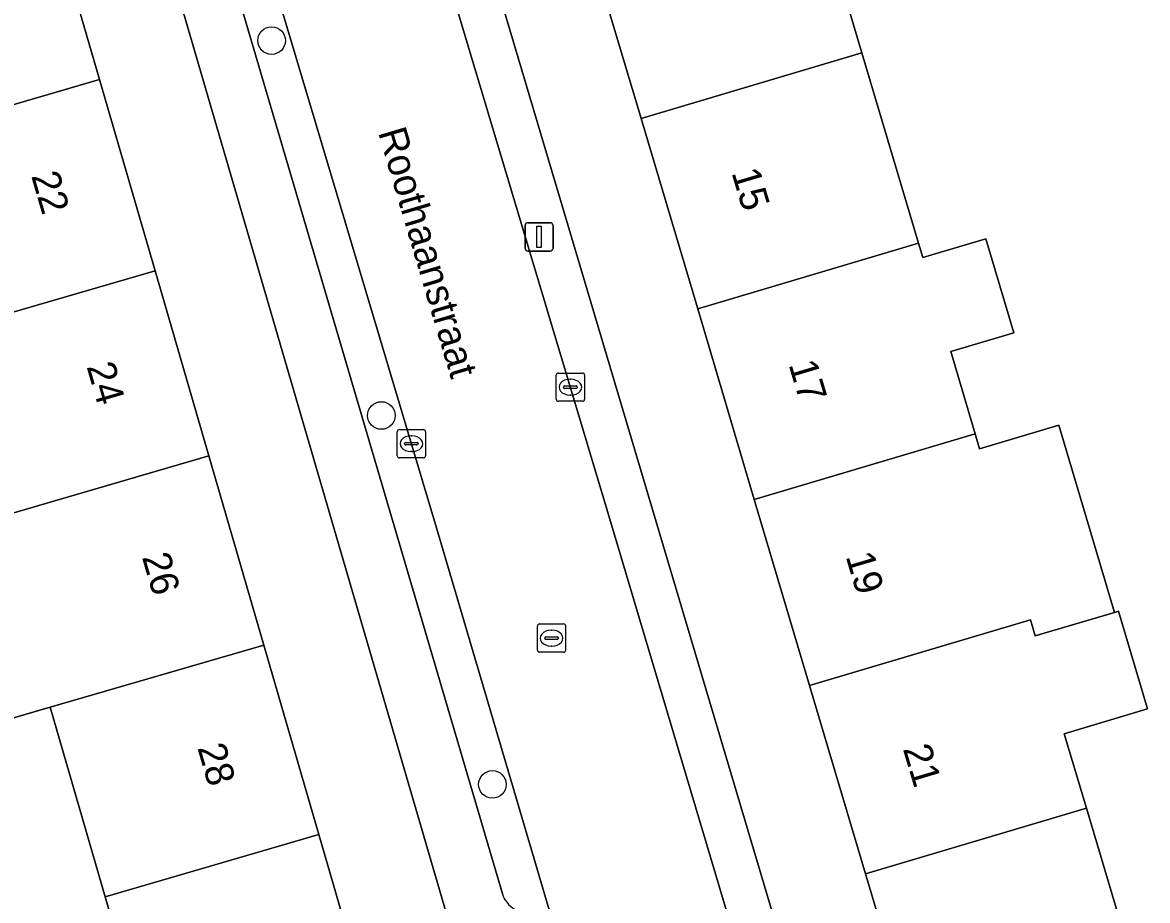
# Model space of a CAD drawing. Extents: x 162523 to 163266, y 381230 to 382050.
# Drawn here: x 162914.84 to 162954.65, y 381817.31 to 381848.37 of the extents above; entities that cross this region are included whole.
import ezdxf

# ---------------------------------------------------------------- set-up
doc = ezdxf.new("R2010")
doc.units = 0
for name, color, linetype in [('IMGEO_Boom', 7, 'Continuous'), ('IMGEO_Erf', 7, 'Continuous'), ('IMGEO_Kolk', 7, 'Continuous'), ('IMGEO_Lichtmast', 7, 'Continuous'), ('IMGEO_Openbare_ruimte_label', 7, 'Continuous'), ('IMGEO_Pand', 7, 'Continuous'), ('IMGEO_Pand_nummerreeks', 7, 'Continuous'), ('IMGEO_Parkeervlak_open', 7, 'Continuous'), ('IMGEO_Rijbaan_lokaal_open', 7, 'Continuous'), ('IMGEO_Rioolput', 7, 'Continuous'), ('IMGEO_Voetpad_open', 7, 'Continuous')]:
    doc.layers.add(name, color=color, linetype=linetype)

msp = doc.modelspace()

# ---------------------------------------------------------------- linework, layer by layer
at = {"layer": 'IMGEO_Boom'}
for centre in [(162923.656, 381847.732), (162927.542, 381834.469), (162931.471, 381821.418)]:
    msp.add_circle(centre, 0.489, dxfattribs=at)
at = {"layer": 'IMGEO_Erf'}
for points in [[(162932.72, 381806.989), (162913.026, 381874.412), (162910.321, 381883.674), (162887.637, 381875.013), (162889.095, 381870.525), (162889.197, 381870.214), (162891.814, 381871.071), (162892.93, 381867.664), (162890.312, 381866.807), (162890.373, 381866.622), (162891.358, 381863.669), (162894.356, 381864.689), (162895.466, 381861.425), (162896.618, 381858.037), (162893.62, 381857.017), (162899.056, 381840.02), (162905.21, 381821.822), (162911.331, 381802.421)], [(162913.666, 381859.797), (162915.626, 381853.053), (162917.573, 381846.353), (162919.539, 381839.585), (162921.441, 381833.041), (162923.387, 381826.346), (162925.334, 381819.645), (162927.278, 381812.956)], [(162942.534, 381854.047), (162944.541, 381847.299), (162946.546, 381840.56), (162946.697, 381840.054), (162948.932, 381840.718), (162949.92, 381837.396), (162947.685, 381836.731), (162948.549, 381833.825), (162948.707, 381833.295), (162951.508, 381834.128), (162953.478, 381827.505), (162953.621, 381827.547), (162954.649, 381824.087), (162951.705, 381823.212), (162952.49, 381820.574), (162954.728, 381813.049)], [(162919.718, 381810.759), (162917.774, 381817.447), (162915.827, 381824.149), (162913.064, 381823.346)]]:
    msp.add_lwpolyline(points, dxfattribs=at)
msp.add_lwpolyline([(162938.733, 381838.237), (162936.729, 381844.976), (162934.721, 381851.724), (162932.793, 381858.209), (162929.389, 381857.197), (162943.516, 381809.691), (162946.922, 381810.704), (162944.677, 381818.251), (162942.694, 381824.919), (162940.736, 381831.502)], close=True, dxfattribs=at)
at = {"layer": 'IMGEO_Kolk'}
for p, q in [((162933.729, 381835.045), (162933.729, 381835.897)), ((162933.804, 381835.971), (162934.656, 381835.971)), ((162934.73, 381835.897), (162934.73, 381835.045)), ((162933.988, 381835.465), (162933.988, 381835.477)), ((162934.031, 381835.514), (162934.429, 381835.514)), ((162934.217, 381835.751), (162934.242, 381835.751)), ((162934.472, 381835.477), (162934.472, 381835.465)), ((162934.426, 381835.428), (162934.028, 381835.428)), ((162934.24, 381835.191), (162934.215, 381835.191)), ((162934.656, 381834.971), (162933.804, 381834.971)), ((162928.103, 381833.045), (162928.103, 381833.897)), ((162928.178, 381833.971), (162929.03, 381833.971)), ((162929.104, 381833.897), (162929.104, 381833.045)), ((162928.362, 381833.465), (162928.362, 381833.477)), ((162928.405, 381833.514), (162928.803, 381833.514)), ((162928.591, 381833.751), (162928.616, 381833.751)), ((162928.846, 381833.477), (162928.846, 381833.465)), ((162928.8, 381833.428), (162928.402, 381833.428)), ((162928.614, 381833.191), (162928.589, 381833.191)), ((162929.03, 381832.971), (162928.178, 381832.971))]:
    msp.add_line(p, q, dxfattribs=at)
for points in [[(162933.729, 381835.045), (162933.729, 381835.897)], [(162933.804, 381835.971), (162934.656, 381835.971)], [(162934.73, 381835.897), (162934.73, 381835.045)], [(162934.656, 381834.971), (162933.804, 381834.971)], [(162928.103, 381833.045), (162928.103, 381833.897)], [(162928.178, 381833.971), (162929.03, 381833.971)], [(162929.104, 381833.897), (162929.104, 381833.045)], [(162929.03, 381832.971), (162928.178, 381832.971)]]:
    msp.add_lwpolyline(points, dxfattribs=at)
for centre, radius, start, end in [((162933.806, 381835.895), 0.0765, 91.552, 178.448), ((162933.806, 381835.895), 0.0765, 91.552, 178.448), ((162934.654, 381835.895), 0.0765, 1.552, 88.448), ((162934.654, 381835.895), 0.0765, 1.552, 88.448), ((162934.028, 381835.474), 0.0403, 85.8775, 175.7526), ((162934.025, 381835.464), 0.0366, 178.938, 274.7102), ((162934.429, 381835.471), 0.043, 264.8664, 352.4533), ((162934.433, 381835.476), 0.0386, 1.7309, 96.639), ((162933.806, 381835.047), 0.0765, 181.552, 268.448), ((162933.806, 381835.047), 0.0765, 181.552, 268.448), ((162934.654, 381835.047), 0.0765, 271.552, 358.448), ((162934.654, 381835.047), 0.0765, 271.552, 358.448), ((162928.18, 381833.895), 0.0765, 91.552, 178.448), ((162928.18, 381833.895), 0.0765, 91.552, 178.448), ((162929.028, 381833.895), 0.0765, 1.552, 88.448), ((162929.028, 381833.895), 0.0765, 1.552, 88.448), ((162928.402, 381833.474), 0.0403, 85.8775, 175.7526), ((162928.399, 381833.464), 0.0366, 178.938, 274.7102), ((162928.803, 381833.471), 0.043, 264.8664, 352.4533), ((162928.807, 381833.476), 0.0386, 1.7309, 96.639), ((162928.18, 381833.047), 0.0765, 181.552, 268.448), ((162928.18, 381833.047), 0.0765, 181.552, 268.448), ((162929.028, 381833.047), 0.0765, 271.552, 358.448), ((162929.028, 381833.047), 0.0765, 271.552, 358.448)]:
    msp.add_arc(centre, radius, start, end, dxfattribs=at)
for centre, major_axis, ratio, start_param, end_param in [((162934.216, 381835.471), (-0.387, 0.002), 0.722429, 4.712389, 7.853982), ((162934.241, 381835.471), (-0.39, 0.002), 0.717154, 1.570796, 4.712389), ((162928.59, 381833.471), (-0.387, 0.002), 0.722429, 4.712389, 7.853982), ((162928.615, 381833.471), (-0.39, 0.002), 0.717154, 1.570796, 4.712389)]:
    msp.add_ellipse(centre, major_axis=major_axis, ratio=ratio, start_param=start_param, end_param=end_param, dxfattribs=at)
at = {"layer": 'IMGEO_Lichtmast'}
for p, q in [((162932.625, 381840.387), (162932.625, 381841.187)), ((162932.625, 381841.187), (162932.625, 381840.387)), ((162932.725, 381841.287), (162933.515, 381841.287)), ((162933.515, 381841.287), (162932.725, 381841.287)), ((162933.615, 381841.187), (162933.615, 381840.387)), ((162933.615, 381840.387), (162933.615, 381841.187)), ((162933.515, 381840.287), (162932.725, 381840.287)), ((162932.725, 381840.287), (162933.515, 381840.287))]:
    msp.add_line(p, q, dxfattribs=at)
msp.add_lwpolyline([(162933.045, 381841.162), (162933.195, 381841.162), (162933.195, 381840.412), (162933.045, 381840.412), (162933.045, 381841.162)], dxfattribs=at)
for centre, start, end in [((162932.725, 381841.187), 90, 180), ((162932.725, 381841.187), 90, 180), ((162933.515, 381841.187), 0, 90), ((162933.515, 381841.187), 360, 90), ((162932.725, 381840.387), 180, 270), ((162932.725, 381840.387), 180, 270), ((162933.515, 381840.387), 270, 0), ((162933.515, 381840.387), 270, 0)]:
    msp.add_arc(centre, 0.1, start, end, dxfattribs=at)
at = {"layer": 'IMGEO_Pand'}
for points in [[(162936.729, 381844.976), (162944.541, 381847.299), (162942.534, 381854.047), (162934.721, 381851.724)], [(162908.066, 381850.856), (162910.013, 381844.155), (162917.573, 381846.353), (162915.626, 381853.053)], [(162946.546, 381840.56), (162944.541, 381847.299), (162936.729, 381844.976), (162938.733, 381838.237)], [(162917.573, 381846.353), (162910.013, 381844.155), (162907.798, 381843.511), (162909.765, 381836.744), (162911.98, 381837.388), (162919.539, 381839.585)], [(162946.546, 381840.56), (162938.733, 381838.237), (162940.736, 381831.502), (162948.549, 381833.825), (162947.685, 381836.731), (162949.92, 381837.396), (162948.932, 381840.718), (162946.697, 381840.054)], [(162919.539, 381839.585), (162911.98, 381837.388), (162909.765, 381836.744), (162911.667, 381830.199), (162913.882, 381830.843), (162921.441, 381833.041)], [(162948.549, 381833.825), (162940.736, 381831.502), (162942.694, 381824.919), (162950.507, 381827.243), (162950.677, 381826.672), (162953.478, 381827.505), (162951.508, 381834.128), (162948.707, 381833.295)], [(162921.441, 381833.041), (162913.882, 381830.843), (162911.667, 381830.199), (162911.119, 381830.04), (162913.064, 381823.346), (162915.827, 381824.149), (162923.387, 381826.346)], [(162954.649, 381824.087), (162953.621, 381827.547), (162953.478, 381827.505), (162950.677, 381826.672), (162950.507, 381827.243), (162942.694, 381824.919), (162944.677, 381818.251), (162952.49, 381820.574), (162951.705, 381823.212)], [(162915.827, 381824.149), (162917.774, 381817.447), (162925.334, 381819.645), (162923.387, 381826.346)], [(162944.677, 381818.251), (162946.922, 381810.704), (162947.276, 381810.809), (162947.158, 381811.205), (162951.951, 381812.63), (162954.218, 381813.304), (162954.329, 381812.93), (162954.728, 381813.049), (162952.49, 381820.574)], [(162917.774, 381817.447), (162919.718, 381810.759), (162927.278, 381812.956), (162925.334, 381819.645)]]:
    msp.add_lwpolyline(points, close=True, dxfattribs=at)
at = {"layer": 'IMGEO_Parkeervlak_open'}
for points in [[(162929.495, 381830.491), (162923.481, 381850.642), (162919.376, 381864.437)], [(162920.468, 381856.125), (162931.824, 381817.55)], [(162940.933, 381791.879), (162939.272, 381797.593), (162935.047, 381811.667), (162929.495, 381830.491)]]:
    msp.add_lwpolyline(points, dxfattribs=at)
msp.add_arc((162932.723, 381817.822), 0.939, 196.8462, 239.9809, dxfattribs=at)
at = {"layer": 'IMGEO_Rijbaan_lokaal_open'}
for points in [[(162946.337, 381789.764), (162947.14, 381791.276), (162946.232, 381794.364), (162943.251, 381805.194), (162942.322, 381808.313), (162935.521, 381831.16), (162928.526, 381854.515), (162924.919, 381866.714)], [(162919.376, 381864.437), (162923.481, 381850.642), (162929.495, 381830.491), (162935.047, 381811.667), (162939.272, 381797.593), (162940.933, 381791.879), (162942.362, 381787.078), (162946.251, 381788.155), (162946.175, 381788.444)]]:
    msp.add_lwpolyline(points, dxfattribs=at)
at = {"layer": 'IMGEO_Rioolput'}
for p, q in [((162933.136, 381827.094), (162933.988, 381827.094)), ((162933.061, 381826.168), (162933.061, 381827.02)), ((162933.549, 381826.874), (162933.574, 381826.874)), ((162934.062, 381827.02), (162934.062, 381826.168)), ((162933.32, 381826.588), (162933.32, 381826.6)), ((162933.758, 381826.551), (162933.36, 381826.551)), ((162933.363, 381826.637), (162933.761, 381826.637)), ((162933.572, 381826.314), (162933.547, 381826.314)), ((162933.804, 381826.6), (162933.804, 381826.588)), ((162933.988, 381826.094), (162933.136, 381826.094))]:
    msp.add_line(p, q, dxfattribs=at)
for points in [[(162933.136, 381827.094), (162933.988, 381827.094)], [(162933.061, 381826.168), (162933.061, 381827.02)], [(162934.062, 381827.02), (162934.062, 381826.168)], [(162933.988, 381826.094), (162933.136, 381826.094)]]:
    msp.add_lwpolyline(points, dxfattribs=at)
for centre, radius, start, end in [((162933.138, 381827.018), 0.0765, 91.552, 178.448), ((162933.138, 381827.018), 0.0765, 91.552, 178.448), ((162933.986, 381827.018), 0.0765, 1.552, 88.448), ((162933.986, 381827.018), 0.0765, 1.552, 88.448), ((162933.36, 381826.597), 0.0403, 85.8775, 175.7526), ((162933.357, 381826.587), 0.0366, 178.938, 274.7102), ((162933.761, 381826.594), 0.043, 264.8664, 352.4533), ((162933.765, 381826.599), 0.0386, 1.7309, 96.639), ((162933.138, 381826.17), 0.0765, 181.552, 268.448), ((162933.138, 381826.17), 0.0765, 181.552, 268.448), ((162933.986, 381826.17), 0.0765, 271.552, 358.448), ((162933.986, 381826.17), 0.0765, 271.552, 358.448)]:
    msp.add_arc(centre, radius, start, end, dxfattribs=at)
for centre, major_axis, ratio, start_param, end_param in [((162933.548, 381826.594), (-0.387, 0.002), 0.722429, 4.712389, 7.853982), ((162933.573, 381826.594), (-0.39, 0.002), 0.717154, 1.570796, 4.712389)]:
    msp.add_ellipse(centre, major_axis=major_axis, ratio=ratio, start_param=start_param, end_param=end_param, dxfattribs=at)
at = {"layer": 'IMGEO_Voetpad_open'}
for points in [[(162942.548, 381907.783), (162932.776, 381896.712), (162917.749, 381879.811), (162913.026, 381874.412), (162932.72, 381806.989), (162933.197, 381805.356), (162934.087, 381802.294), (162936.402, 381794.569), (162939.195, 381785.063), (162942.653, 381786.062), (162942.362, 381787.078), (162940.933, 381791.879)], [(162924.919, 381866.714), (162928.526, 381854.515), (162935.521, 381831.16), (162942.322, 381808.313), (162942.8, 381808.456), (162943.729, 381805.337), (162943.251, 381805.194), (162946.232, 381794.364), (162947.14, 381791.276), (162946.337, 381789.764)], [(162945.842, 381801.764), (162944.706, 381805.688), (162943.773, 381808.826), (162943.516, 381809.691), (162929.389, 381857.197), (162929.077, 381858.247), (162926.976, 381865.311)], [(162931.824, 381817.55), (162920.468, 381856.125)]]:
    msp.add_lwpolyline(points, dxfattribs=at)
msp.add_arc((162932.723, 381817.822), 0.939, 196.8462, 239.9809, dxfattribs=at)

# ---------------------------------------------------------------- texts
at = {"layer": 'IMGEO_Openbare_ruimte_label'}
msp.add_text('Roothaanstraat', height=1, rotation=286.4962, dxfattribs=at).set_placement((162927.418, 381844.492))
at = {"layer": 'IMGEO_Pand_nummerreeks'}
for s, rotation, p in [('22', 286.203, (162915.146, 381842.948)), ('15', 286.5641, (162939.926, 381843.063)), ('24', 286.203, (162917.106, 381836.204)), ('17', 286.564, (162941.945, 381836.277)), ('26', 286.203, (162919.065, 381829.463)), ('19', 286.564, (162943.963, 381829.49)), ('28', 286.2035, (162921.026, 381822.719)), ('21', 286.564, (162945.989, 381822.682))]:
    msp.add_text(s, height=1, rotation=rotation, dxfattribs=at).set_placement(p)

doc.saveas('drawing.dxf')
